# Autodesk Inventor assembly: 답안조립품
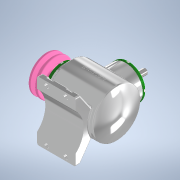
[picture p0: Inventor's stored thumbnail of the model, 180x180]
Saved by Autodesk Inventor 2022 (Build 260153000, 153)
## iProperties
Created: 2023-04
Part Number: 답안조립품
Document SubType Name: Assembly
Designer: Admin
Author: Admin
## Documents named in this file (17)
- C:\Users\Admin\Desktop\730411V1014\답안조립품.iam
- C:\Users\Admin\Desktop\730411V1014\본체.ipt
- C:\Users\Admin\Desktop\730411V1014\730411V1014\커버.ipt
- C:\Users\Admin\Desktop\730411V1014\730411V1014\베어링 6203.ipt
- C:\Users\Admin\Desktop\730411V1014\730411V1014\오일실 17 x 32 x 8.ipt
- C:\Users\Admin\Desktop\730411V1014\730411V1014\메인 축.ipt
- 메인 축.ipt
- C:\Users\Admin\Desktop\730411V1014\730411V1014\키 5 x 5 x 14.ipt
- C:\Users\Admin\Desktop\730411V1014\730411V1014\메인 베벨기어.ipt
- C:\Users\Admin\Desktop\730411V1014\730411V1014\서브 축.ipt
- 서브 축.ipt
- C:\Users\Admin\Desktop\730411V1014\730411V1014\키 4 x 4 x 14.ipt
- C:\Users\Admin\Desktop\730411V1014\730411V1014\서브 베벨기어.ipt
- C:\Users\Admin\Desktop\730411V1014\730411V1014\와셔 4 x 16.ipt
- C:\Users\Admin\Desktop\730411V1014\730411V1014\V-벨트풀리.ipt
- C:\Users\Admin\Desktop\730411V1014\730411V1014\볼트 M4 x 10.ipt
- C:\Users\Admin\Desktop\730411V1014\730411V1014\육각볼트 M4 x 8.ipt
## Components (1 placed, 1 different names)
1. V-벨트풀리:1
